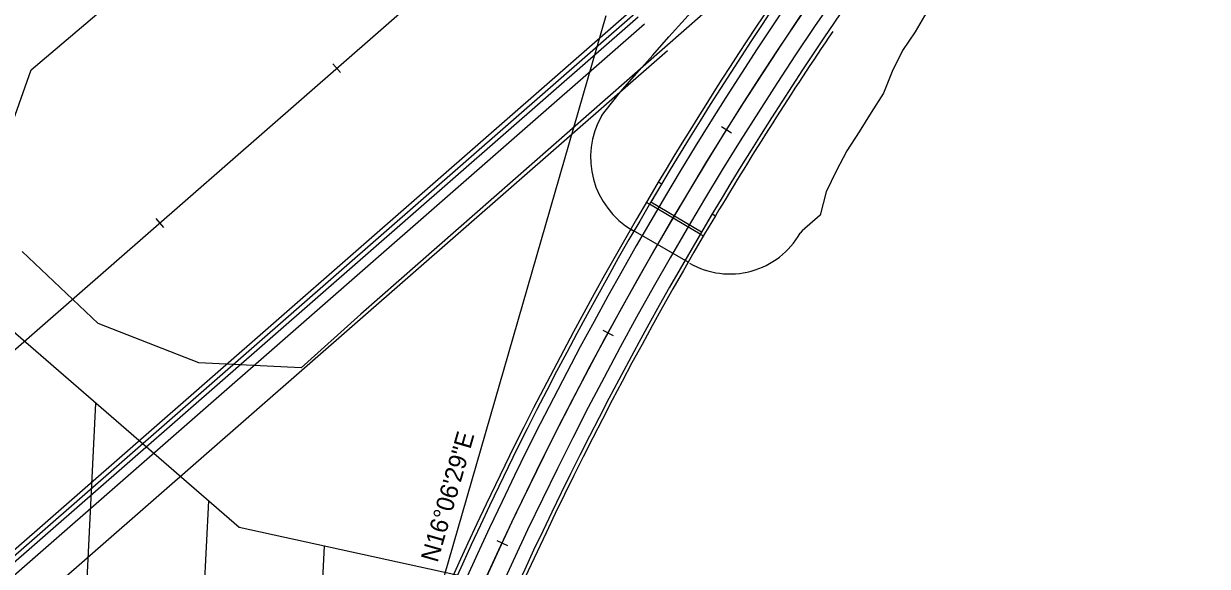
# Model space of a CAD drawing. Extents: x 1300404 to 1323571, y 237813 to 252077.
# Drawn here: x 1311456 to 1311959, y 241490 to 241720 of the extents above; entities that cross this region are included whole.
import ezdxf

# ---------------------------------------------------------------- set-up
doc = ezdxf.new("R2010")
doc.units = 0
for name, color, linetype in [('R_Bridge', 7, 'Continuous'), ('R_Const Limits', 7, 'Continuous'), ('R_Floodway', 7, 'Continuous'), ('R_Flooplain', 7, 'Continuous'), ('R_Future', 7, 'Continuous'), ('R_Guardrail', 7, 'Continuous'), ('R_Horz Alg Minor Ticks', 7, 'Continuous'), ('R_Horz Alg Tangents', 7, 'Continuous'), ('R_Horz Alg Tangents Text', 7, 'Continuous'), ('R_Lane Edge', 7, 'Continuous'), ('R_Proposed', 7, 'Continuous'), ('R_Shoulder', 7, 'Continuous')]:
    doc.layers.add(name, color=color, linetype=linetype)

msp = doc.modelspace()

# ---------------------------------------------------------------- linework, layer by layer
at = {"layer": 'R_Bridge'}
for p, q in [((1311727.32, 241652.29), (1311725.96, 241653.1)), ((1311722.22, 241643.69), (1311720.86, 241644.49)), ((1311743.77, 241631), (1311722.22, 241643.69)), ((1311744.27, 241631.87), (1311722.73, 241644.55)), ((1311748.86, 241639.61), (1311750.22, 241638.81)), ((1311743.77, 241631), (1311745.13, 241630.2))]:
    msp.add_line(p, q, dxfattribs=at)
for radius, start, end in [(1650.1, 149.19442, 159.34505), (1648.52, 149.19413, 159.34535), (1623.52, 149.18931, 159.35016), (1621.94, 149.189, 159.35047)]:
    msp.add_arc((1313143.24, 240808.04), radius, start, end, dxfattribs=at)
at = {"layer": 'R_Const Limits'}
msp.add_line((1311738.61, 241619.01), (1311714.22, 241633.09), dxfattribs=at)
for points in [[(1311701.9, 241681.46), (1311703.4, 241683.31), (1311709.85, 241691.43), (1311716.7, 241699.28), (1311723.55, 241707.1), (1311730.41, 241714.9), (1311737.4, 241722.58), (1311744.27, 241730.33), (1311750.83, 241738.25), (1311752.75, 241749.31), (1311755.88, 241759.59), (1311758.29, 241763.87)], [(1311840, 241725.51), (1311835.13, 241717.04), (1311829.64, 241709.01), (1311825.3, 241700.19), (1311821.6, 241690.97), (1311816.44, 241682.74), (1311811.31, 241674.5), (1311806.03, 241666.36), (1311801.44, 241657.77), (1311797.29, 241648.93), (1311794.74, 241639.11), (1311787.05, 241632.46), (1311786.21, 241631.43), (1311786.21, 241631.43)]]:
    msp.add_lwpolyline(points, dxfattribs=at)
for centre, radius, start, end in [((1311733.02, 241663.64), 35.86, 150.212, 239.9997), ((1311756.39, 241648.34), 34.28, 239.9997, 330.4542)]:
    msp.add_arc(centre, radius, start, end, dxfattribs=at)
at = {"layer": 'R_Floodway'}
for p, q in [((1311480.45, 241428.78), (1311486.99, 241559.2)), ((1311529.43, 241407.02), (1311534.97, 241517.61)), ((1311578.53, 241387.86), (1311584.07, 241498.53))]:
    msp.add_line(p, q, dxfattribs=at)
msp.add_lwpolyline([(1310379.63, 242680.75), (1310490.18, 242568.72), (1310548.96, 242534.3), (1310676.05, 242414.18), (1310731.56, 242362.99), (1310810.26, 242291.28), (1310887.62, 242241.41), (1310974.87, 242195.88), (1311031.59, 242168.82), (1311109.67, 242133.43), (1311173.76, 242108.43), (1311242.66, 242083.18), (1311339.33, 242032.34), (1311351.04, 242024.49), (1311431.54, 241940.59), (1311405.15, 241750.77), (1311416.02, 241677.63), (1311441.14, 241598.94), (1311547.83, 241506.46), (1311691.44, 241475.03), (1311836.73, 241477.39), (1311974.41, 241472.87)], dxfattribs=at)
at = {"layer": 'R_Flooplain'}
for p, q in [((1311459.52, 241700.85), (1312470.12, 242559.7)), ((1312629.3, 242500.87), (1311599.52, 241597.01)), ((1311442.64, 241653.31), (1311459.52, 241700.85)), ((1311488.02, 241592.95), (1311455.67, 241623.61)), ((1311599.52, 241597.01), (1311574.18, 241574.09)), ((1311530.74, 241576.28), (1311488.02, 241592.95)), ((1311574.18, 241574.09), (1311530.74, 241576.28))]:
    msp.add_line(p, q, dxfattribs=at)
at = {"layer": 'R_Future'}
for p, q in [((1311714.76, 241726.24), (1309950.43, 240183.5)), ((1311716.07, 241724.73), (1309951.75, 240181.99)), ((1311717.39, 241723.23), (1309953.06, 240180.49)), ((1311720.02, 241720.22), (1309955.69, 240177.48)), ((1311729.9, 241708.92), (1311093.16, 241152.15))]:
    msp.add_line(p, q, dxfattribs=at)
at = {"layer": 'R_Guardrail'}
for centre, radius, start, end in [((1313143.24, 240808.04), 1650.1, 142.0428, 149.19537), ((1313143.25, 240808.04), 1621.94, 145.90788, 149.18929)]:
    msp.add_arc(centre, radius, start, end, dxfattribs=at)
at = {"layer": 'R_Horz Alg Minor Ticks'}
for points in [[(1311587.68, 241703.45), (1311590.97, 241699.69)], [(1311752.78, 241676.73), (1311757.02, 241674.09)], [(1311512.4, 241637.63), (1311515.69, 241633.86)], [(1311702.34, 241590.23), (1311706.74, 241587.84)], [(1311657.28, 241500.8), (1311661.81, 241498.69)]]:
    msp.add_lwpolyline(points, dxfattribs=at)
at = {"layer": 'R_Horz Alg Tangents'}
msp.add_line((1311570.49, 241262.23), (1311703.85, 241724), dxfattribs=at)
at = {"layer": 'R_Lane Edge'}
for radius, start in [(1629.52, 131.16667), (1644.52, 136.45181), (1644.52, 136.45181)]:
    msp.add_arc((1313143.24, 240808.04), radius, start, 163.89183, dxfattribs=at)
at = {"layer": 'R_Proposed'}
for p, q in [((1308427.57, 238936.91), (1312793.8, 242754.77)), ((1309180.37, 239595.16), (1312398.96, 242409.52))]:
    msp.add_line(p, q, dxfattribs=at)
for end in [163.89183, 163.04191]:
    msp.add_arc((1313143.24, 240808.04), 1637.02, 131.16667, end, dxfattribs=at)
at = {"layer": 'R_Shoulder'}
for radius, start in [(1623.52, 131.16667), (1648.52, 140.49476)]:
    msp.add_arc((1313143.24, 240808.04), radius, start, 149.50693, dxfattribs=at)

# ---------------------------------------------------------------- texts
at = {"layer": 'R_Horz Alg Tangents Text'}
msp.add_text('N16%%d06\'29"E', height=7.5, rotation=73.8918, dxfattribs=at).set_placement((1311632.12, 241491.06))

doc.saveas('drawing.dxf')
